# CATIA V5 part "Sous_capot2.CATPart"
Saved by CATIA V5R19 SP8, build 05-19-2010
Part number: Sous_capot2
Bounding box of the stored display mesh (mm): x -3 to 20, y -114 to 114, z -113.807 to 113.807
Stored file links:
  G:\EU_thinkMotion\CFAO_2010\SIL_groupe2\SIL_groupe2\msauret\Brevet_Sauret_parametre\Sous_capot2.CATPart
  F:\Brevet_Sauret paramétré\Product3.CATProduct
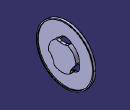
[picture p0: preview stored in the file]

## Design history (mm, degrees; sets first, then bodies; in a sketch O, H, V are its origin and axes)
Set1
  Plane1 to Plane6: linked copy from another document
  Line1: linked copy from another document
Body1 (main body)
  Sketch1 on Plane1, origin (0, 0, 0), H (0, 1, 0), V (0, 0, 1)
    circle A1 centre (0, 0) radius 114
  Pad1: profile Sketch1, direction (1, 0, 0), up to Plane2
  Sketch2 on Plane2, origin (9, 0, 0), H (0, 1, 0), V (0, 0, 1)
    circle A1 centre (0, 0) radius 110
  Pocket1: profile Sketch2, direction (-1, 0, 0), up to Plane3
  Sketch3 on Plane3, origin (5, 0, 0), H (0, 1, 0), V (0, 0, 1)
    circle A1 centre (0, 0) radius 54
  Pad2: profile Sketch3, direction (1, 0, 0), up to Plane4
  Sketch4 on Plane1, origin (0, 0, 0), H (0, 1, 0), V (0, 0, 1)
    circle A1 centre (0, 0) radius 110
  Pad3: profile Sketch4, direction (1, 0, 0), up to Plane5
  Sketch5 on Plane5, origin (-3, 0, 0), H (0, 1, 0), V (0, 0, 1)
    circle A1 centre (0, 0) radius 52
    point P1 (0, 0)
    coincidence: P1 H
  Pocket2: profile Sketch5, direction (-1, 0, 0), up to Plane6
  Sketch6 on Plane5, origin (-3, 0, 0), H (0, 1, 0), V (0, 0, 1)
    line L1 (-22.953, 49.3179) -> (-10, 45)
    line L2 (-10, 45) -> (10, 45)
    line L3 (10, 45) -> (22.9524, 49.318)
    arc A1 centre (0, 30) radius 30 from (22.9524, 49.318) to (-22.9527, 49.3177) ccw
    point P5 (0, 30)
    point P6 (-22.9527, 49.3177)
    horizontal: L2 H
    coincidence: P5 V, L1 P6
  Pocket3: profile Sketch6, direction (-1, 0, 0), up to Plane4
  CircPattern1: of Pocket3, instances 3, angular step 120, axis from Line1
